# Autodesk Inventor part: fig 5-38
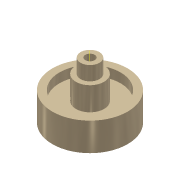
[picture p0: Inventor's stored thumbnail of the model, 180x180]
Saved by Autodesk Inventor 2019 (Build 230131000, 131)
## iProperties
Shininess: 65.0
Length Units: 11269
Angle Units: 11279
Time Units: 11290
Mass Units: 11283
Length Display Precision: 3
Angle Display Precision: 2
Created: 2001-11
Part Number: fig 5-38
Document SubType Name: Modeling
Designer: Renu Muthoo
Density: 1 g/cm^3
Material: Generic
Appearance: Metal-Titanium (Polished)
Density: 0.0
Volumn: 0.0
Area: 0.0
PropertySet Name: Model Information
Control State: 0
Master: False
Checked Out: False
Author: Renu Muthoo
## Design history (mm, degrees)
sketch "Sketch1"
  geometry: L1 (2.694, 30.112)-(5.194, 30.112); L2 (5.194, 30.112)-(5.194, 22.612); L3 (5.194, 22.612)-(7.694, 22.612); L4 (7.694, 22.612)-(7.694, 10.112); L5 (7.694, 10.112)-(16.444, 10.112); L6 (16.444, 10.112)-(16.444, 15.112); L7 (16.444, 15.112)-(20.194, 15.112); L8 (0.194, -4.034)-(0.194, 25.966); L9 (2.694, 30.112)-(2.694, 0.112); L10 (2.694, 0.112)-(20.194, 0.112); L11 (20.194, 0.112)-(20.194, 15.112)
  constraints: 22 end point, 7 parallel, 2 perpendicular, 1 horizontal
  dimensions: "d0" = 5 diameter of L9 L8; "d1" = 10 diameter of L2 L8; "d2" = 15 diameter of L4 L8; "d3" = 32.5 diameter of L6 L8; "d4" = 40 diameter of L11 L8; "d5" = 15 distance of L10.end L7.end; "d6" = 22.5 distance between parallel lines of L3 L10; "d7" = 30 distance between parallel lines of L1 L10; "d8" = 10 distance between parallel lines of L10 L5
revolve "Revolution1" sketch "Sketch1" stored, may be unused: angle "d9" = 90 deg
workaxis "Work Axis1"
node "Sketch3"
workaxis "Work Axis4"
body "Solid1"
